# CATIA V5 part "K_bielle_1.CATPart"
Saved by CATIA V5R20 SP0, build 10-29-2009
Part number: bielle_1
Publications: "Corps principal"
Bounding box of the stored display mesh (mm): x -40 to 40, y 92.698 to 273.769, z 97.354 to 170.305
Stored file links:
  G:\Khaled_CFAO_2011\ST2M\ST2M_GR2\echouteau\Khaled\CAD_ThinkMotion\K_bielle_1.CATPart
  F:\2A\Proj Think Motion\trainv3\Version3\sql_general.CATProduct
  G:\Khaled_CFAO_2011\ST2M\ST2M_GR2\echouteau\Khaled\CAD_ThinkMotion\K_tige.CATPart
  G:\Khaled_CFAO_2011\ST2M\ST2M_GR2\echouteau\Khaled\CAD_ThinkMotion\K_corps.CATPart
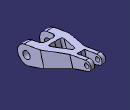
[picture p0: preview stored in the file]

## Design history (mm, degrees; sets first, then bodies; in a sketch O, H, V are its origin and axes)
Set1
  Point1: linked copy from another document
  Point2: linked copy from another document
  Plane1: linked copy from another document
Body1 (main body)
  Point3: type Between, FirstPoint Point1, SecondPoint Point2, Ratio 0.5
  Plane2: type OffsetPt, RefPlane Plane1, RefPoint Point3
  Point4: type OnPlane, Support Plane2, H 0, V 200, Direction (1, 0, 0)
  Line1: type PtPt, FirstPoint Point1, SecondPoint Point4
  Plane3 "Plan_pivot": type Normal, Curve Line1, RefPoint Point1
  Line2: type PtDir, RefPoint Point4, Direction yz-plane, Start 0, End 262
  Plane4: type OffsetPt, RefPlane yz-plane, RefPoint vertex of Line2
  Line3: type PtDir, RefPoint Point1, Direction yz-plane, Start 0, End 262
  Plane5: type OffsetPt, RefPlane yz-plane, RefPoint vertex of Line3
  Sketch1 on yz-plane, origin (0, 0, 0), H (0, 1, 0), V (0, 0, 1)
    arc A1 centre (116.697, 121.3538) radius 24 from (110.6746, 144.5859) to (122.5218, 98.0714) ccw
    point P1 (116.697, 121.3538)
    reference projected point E1 (116.697, 121.3538) from Point1
    arc A2 centre (261.7767, 158.3055) radius 12 from (264.6661, 146.6585) to (258.7426, 169.9155) ccw
    point P2 (261.7767, 158.3055)
    reference projected point E2 (261.7767, 158.3055) from Point4
    line L1 (258.7426, 169.9155) -> (110.6746, 144.5859)
    line L2 (264.6661, 146.6585) -> (122.5218, 98.0714)
    coincidence: P1 E1, P2 E2
  Plane6: type 3Points, Element1 Point1, Element2 Point4, Element3 vertex of Line3
  Sketch2 on Plane6, origin (0, -21.9166, 86.049), H (-1, 0, 0), V (0, 0.9691, 0.2468)
    point P1 (40, 117.5046)
    point P2 (20, 117.5046)
    point P3 (40, 187.5046)
    point P4 (20, 249.3512)
    point P5 (-20, 249.3512)
    point P6 (-40, 187.5046)
    line L1 (-20, 249.3512) -> (-40, 187.5046)
    point P7 (-40, 117.5046)
    point P8 (-20, 117.5046)
    line L2 (-20, 117.5046) -> (-20, 162.5046)
    line L3 (-40, 117.5046) -> (-20, 117.5046)
    line L4 (-10, 172.5046) -> (-0.1715, 172.5046)
    arc A1 centre (-10, 162.5046) radius 10 from (-10, 172.5046) to (-20, 162.5046) ccw
    line L5 (20, 249.3512) -> (40, 187.5046)
    line L6 (40, 187.5046) -> (40, 117.5046)
    line L7 (40, 117.5046) -> (20, 117.5046)
    line L8 (-0.1715, 172.5046) -> (10, 172.5046)
    line L9 (20, 162.5046) -> (20, 117.5046)
    arc A2 centre (10, 162.5046) radius 10 from (10, 172.5046) to (20, 162.5046) cw
    line L10 (20, 249.3512) -> (20, 309.3512)
    point P14 (20, 309.3512)
    line L11 (20, 309.3512) -> (10, 309.3512)
    point P15 (10, 309.3512)
    line L12 (10, 309.3512) -> (10, 259.3512)
    point P16 (10, 259.3512)
    line L13 (10, 259.3512) -> (0, 259.3512)
    point P17 (0, 259.3512)
    point P18 (-20, 309.3512)
    point P19 (-20, 249.3512)
    line L14 (-20, 249.3512) -> (-20, 309.3512)
    point P20 (-10, 309.3512)
    line L15 (-20, 309.3512) -> (-10, 309.3512)
    point P21 (-10, 259.3512)
    line L16 (-10, 309.3512) -> (-10, 259.3512)
    point P22 (0, 259.3512)
    line L17 (-10, 259.3512) -> (0, 259.3512)
    line L18 (-40, 187.5046) -> (-40, 117.5046)
    distance P2 P8 = 40
    distance P1 P7 = 80
    radius A1 = 10
    radius A2 = 10
    length L5 = 65
    length L6 = 70
    distance L8 L7 = 55
    length L10 = 60
    distance P18 P14 = 40
    distance P20 P15 = 20
    length L16 = 50
    symmetry: P4 P5 V, P3 P6 V, P1 P7 V, P2 P8 V, P14 P18 V, P4 P19 V, L10 L14 V, P15 P20 V, L11 L15 V, P16 P21 V, L12 L16 V, P17 P22 V, L13 L17 V
    tangency: A1 L4, A1 L2, L8 A1, A2 L8, A2 L9
    vertical: L6 V, L9 V, L10 V, L12 V, L18 V
    horizontal: L7 H, L11 H, L13 H
    coincidence: P17 V
  SolidCombine1: FirstComponentProfile Sketch1, FirstComponentDirection Sketch1, SecondComponentProfile Sketch2, SecondComponentDirection Sketch2
  Sketch3 on face of SolidCombine1 from Sketch2.L14, origin (20, 265.0272, 153.7365), H (0, 1, 0), V (0, 0, 1)
    point P1 (-3.2506, 4.5689)
    reference projected arc E1 centre (-3.2506, 4.5689) radius 12 from (-0.3611, -7.078) to (-6.2847, 16.179) ccw from Sketch1.A2
    concentricity: P1 E1
  Hole1: placed by Sketch3, at (20, 261.7767, 158.3055) direction (-1, 0, 0), diameter 12, up to face of SolidCombine1 from Sketch2.L10
  Sketch4 on face of SolidCombine1 from Sketch2.L18, origin (40, 105.2361, 129.6602), H (0, 1, 0), V (0, 0, 1)
    point P1 (11.4609, -8.3064)
    reference projected arc E1 centre (11.4609, -8.3064) radius 24 from (5.4385, 14.9257) to (17.2857, -31.5888) ccw from Sketch1.A1
    concentricity: P1 E1
  Hole2: placed by Sketch4, at (40, 116.697, 121.3538) direction (-1, 0, 0), diameter 20, through (limit type 3)
  Sketch5 on face of SolidCombine1 from Sketch1.L2, origin (0, 264.6661, 146.6585), H (0, -0.9462, -0.3234), V (1, 0, 0)
    line L1 (103, 0) -> (103, 14.1076)
    point P1 (103, 0)
    point P2 (103, 21)
    line L2 (96.4481, 18.8607) -> (53.2413, 4.753)
    point P3 (38.6843, 0)
    reference projected line E1 (40.9917, 20) -> (102.2447, 40) from edge [face of SolidCombine1 from Sketch1.L1 | face of SolidCombine1 from Sketch2.L1]
    reference projected line E2 (117.1008, 10) -> (117.1008, 0.1715) from edge [face of SolidCombine1 from Sketch1.L1 | face of SolidCombine1 from Sketch2.L4]
    point P4 (38.6843, 0)
    point P5 (103, -21)
    line L3 (96.4481, -18.8607) -> (53.2413, -4.753)
    point P6 (103, 0)
    line L4 (103, 0) -> (103, -14.1076)
    arc A1 centre (98, 14.1076) radius 5 from (96.4481, 18.8607) to (103, 14.1076) cw
    arc A2 centre (98, -14.1076) radius 5 from (103, -14.1076) to (96.4481, -18.8607) cw
    arc A3 centre (54.7932, 0) radius 5 from (53.2413, 4.753) to (53.2413, -4.753) ccw
    distance P2 P1 = 21
    radius A1 = 5
    radius A2 = 5
    radius A3 = 5
    coincidence: P1 H, P3 H, L2 P2, L1 P2, L4 P5, L3 P5, L2 P3, L3 P4, P1 P6
    vertical: L1 V
    parallelism: E1 L2, L1 E2
    symmetry: P3 P4 H, P2 P5 H, L2 L3 H, P1 P6 H, L1 L4 H
    tangency: A1 L2, A1 L1, A2 L4, A2 L3, A3 L2, A3 L3
  Pocket1: profile Sketch5, direction (0, -0.3234, 0.9462), through (limit type 3)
